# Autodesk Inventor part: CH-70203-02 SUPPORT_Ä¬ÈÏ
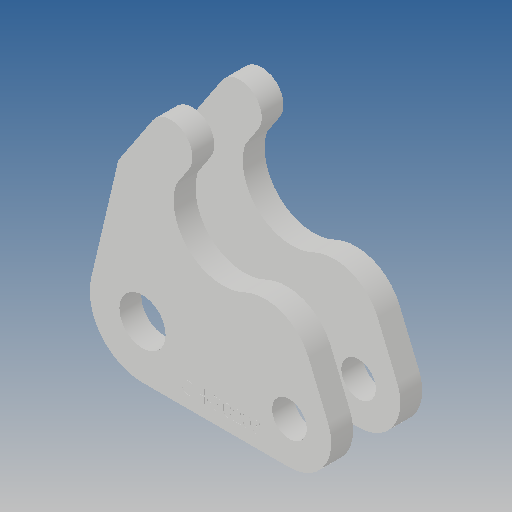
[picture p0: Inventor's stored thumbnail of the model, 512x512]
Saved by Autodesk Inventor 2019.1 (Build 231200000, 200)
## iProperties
Created: 2010-06
Part Number: CH-70203-02 SUPPORT_Ä¬ÈÏ
Material: Ogólny
Document SubType Name: Modeling
Designer: CADENGINEERING4
Density: 1 g/cm^3
Appearance: Domyślna
Author: CADENGINEERING4
Revision Number: ÈÎºÎ
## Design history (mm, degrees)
feature "NONE"
feature "NONE:1"
node "Bryła1"
node "Bryła2"
